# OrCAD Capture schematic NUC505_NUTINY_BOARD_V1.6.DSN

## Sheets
1 Block Diagram: size A; rev: 1.6; note: Block Diagram; note: NUC505 Tiny Board
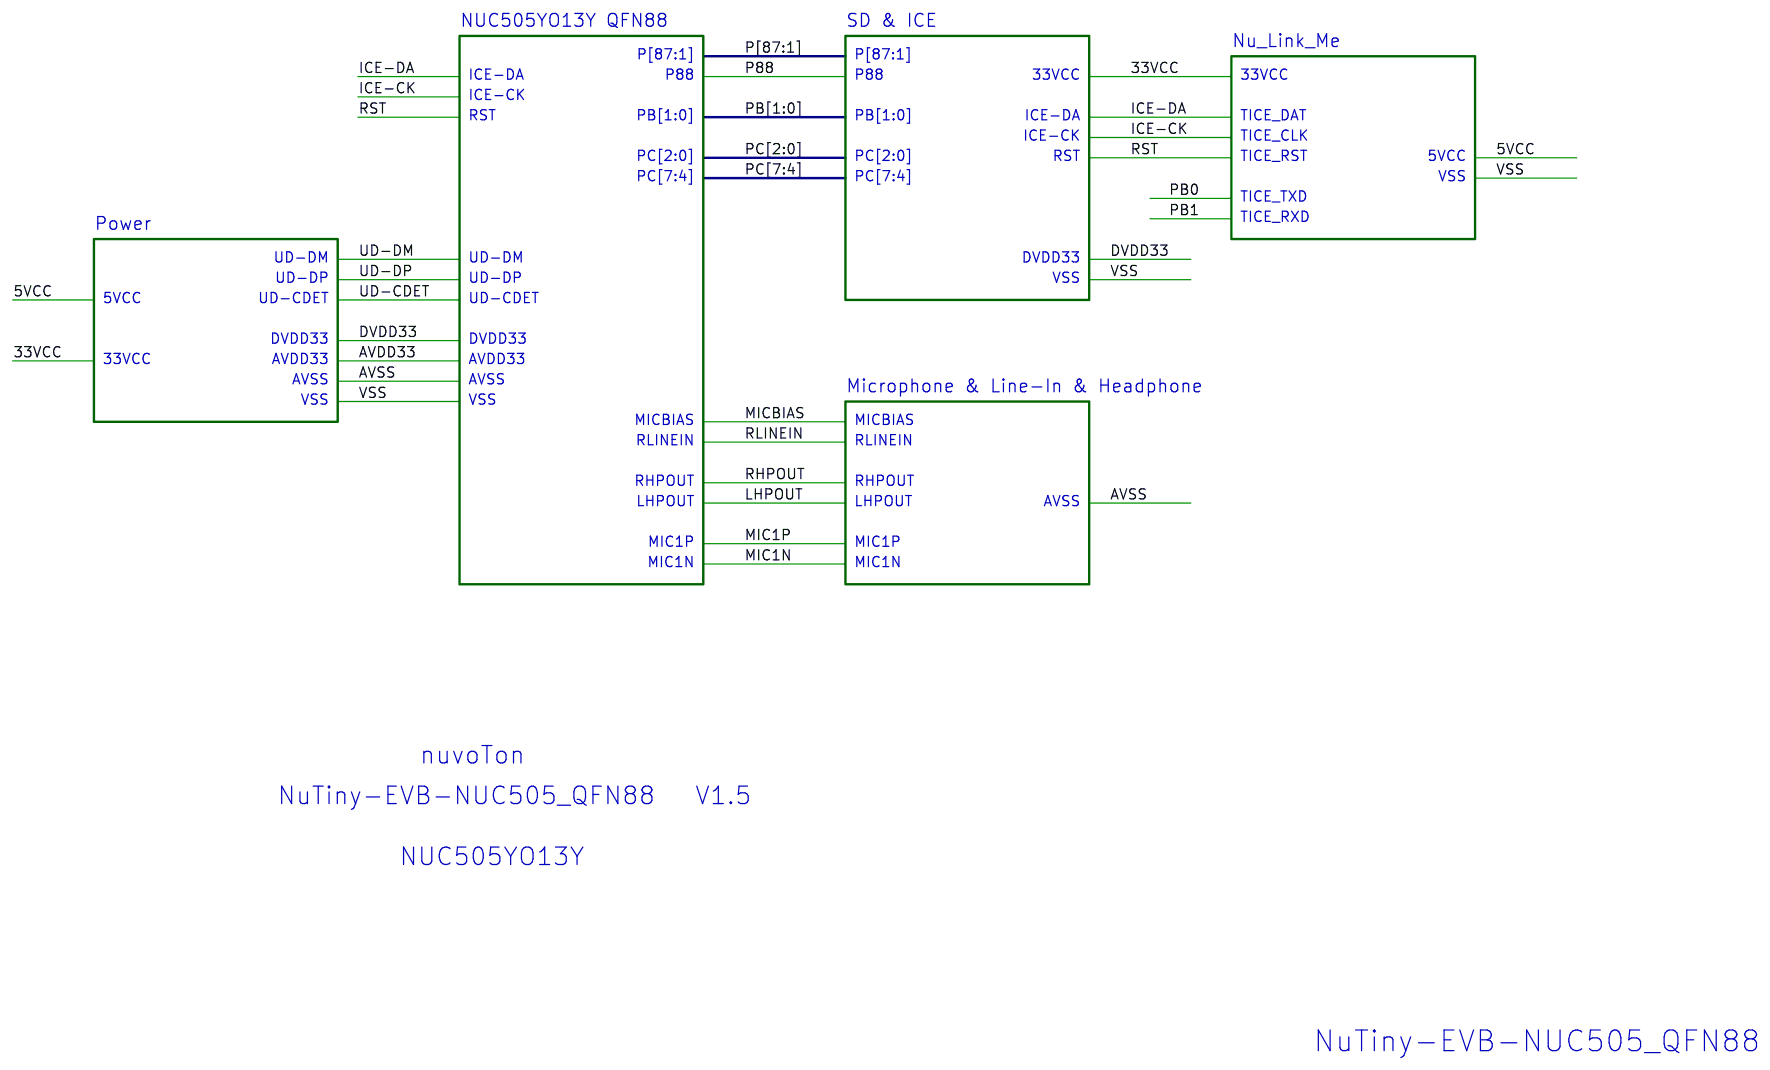
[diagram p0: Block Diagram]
2 Microphone&Line-In&Headphone: size A; note: Microphone&Line In&Headphone; block Microphone & Line-In & Headphone
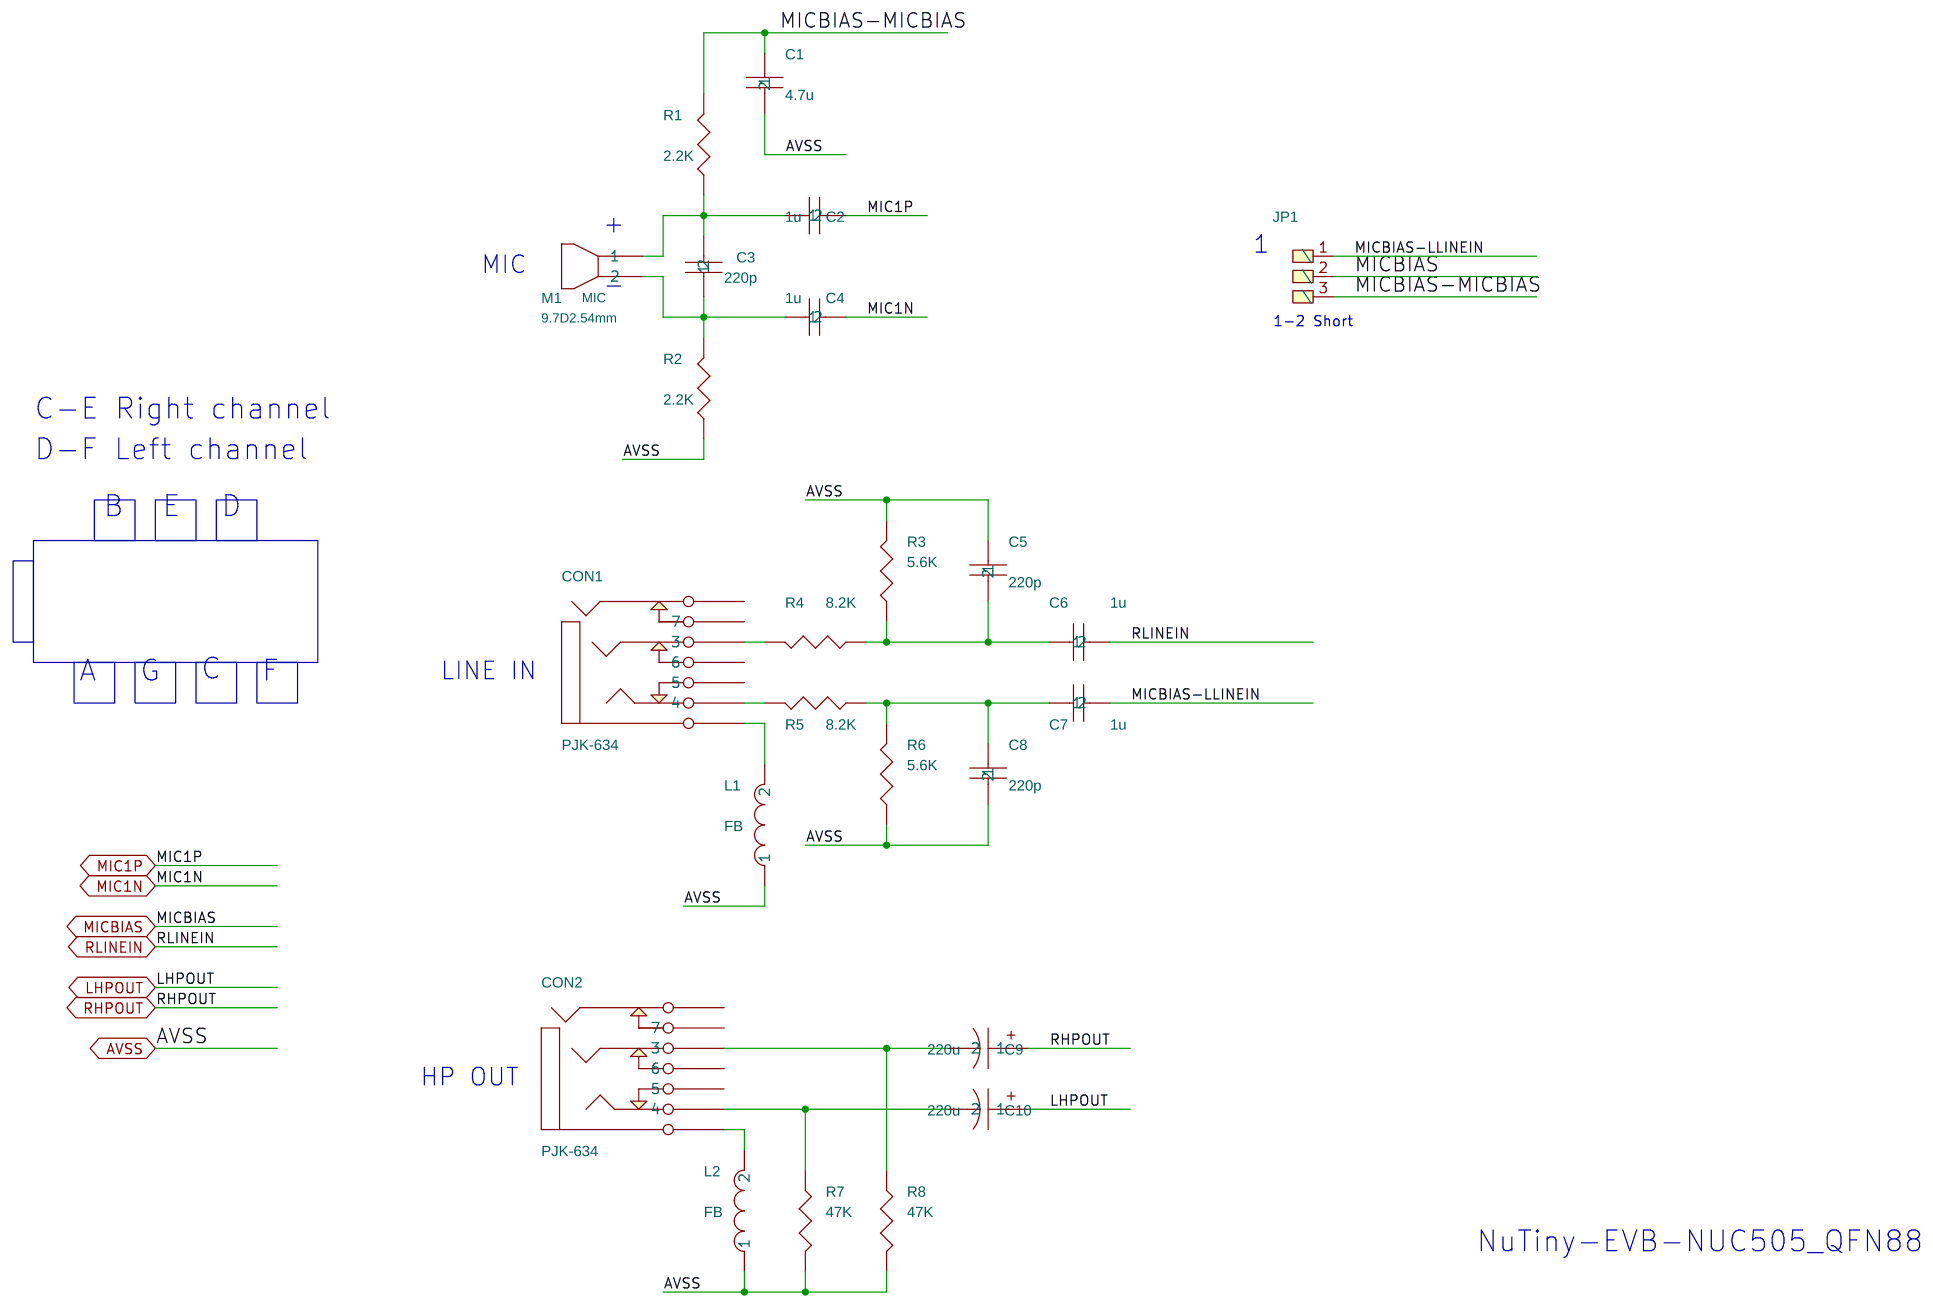
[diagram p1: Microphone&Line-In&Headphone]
3 Nu_Link_Me: size A4; note: Nu_Link_Me; block Nu_Link_Me
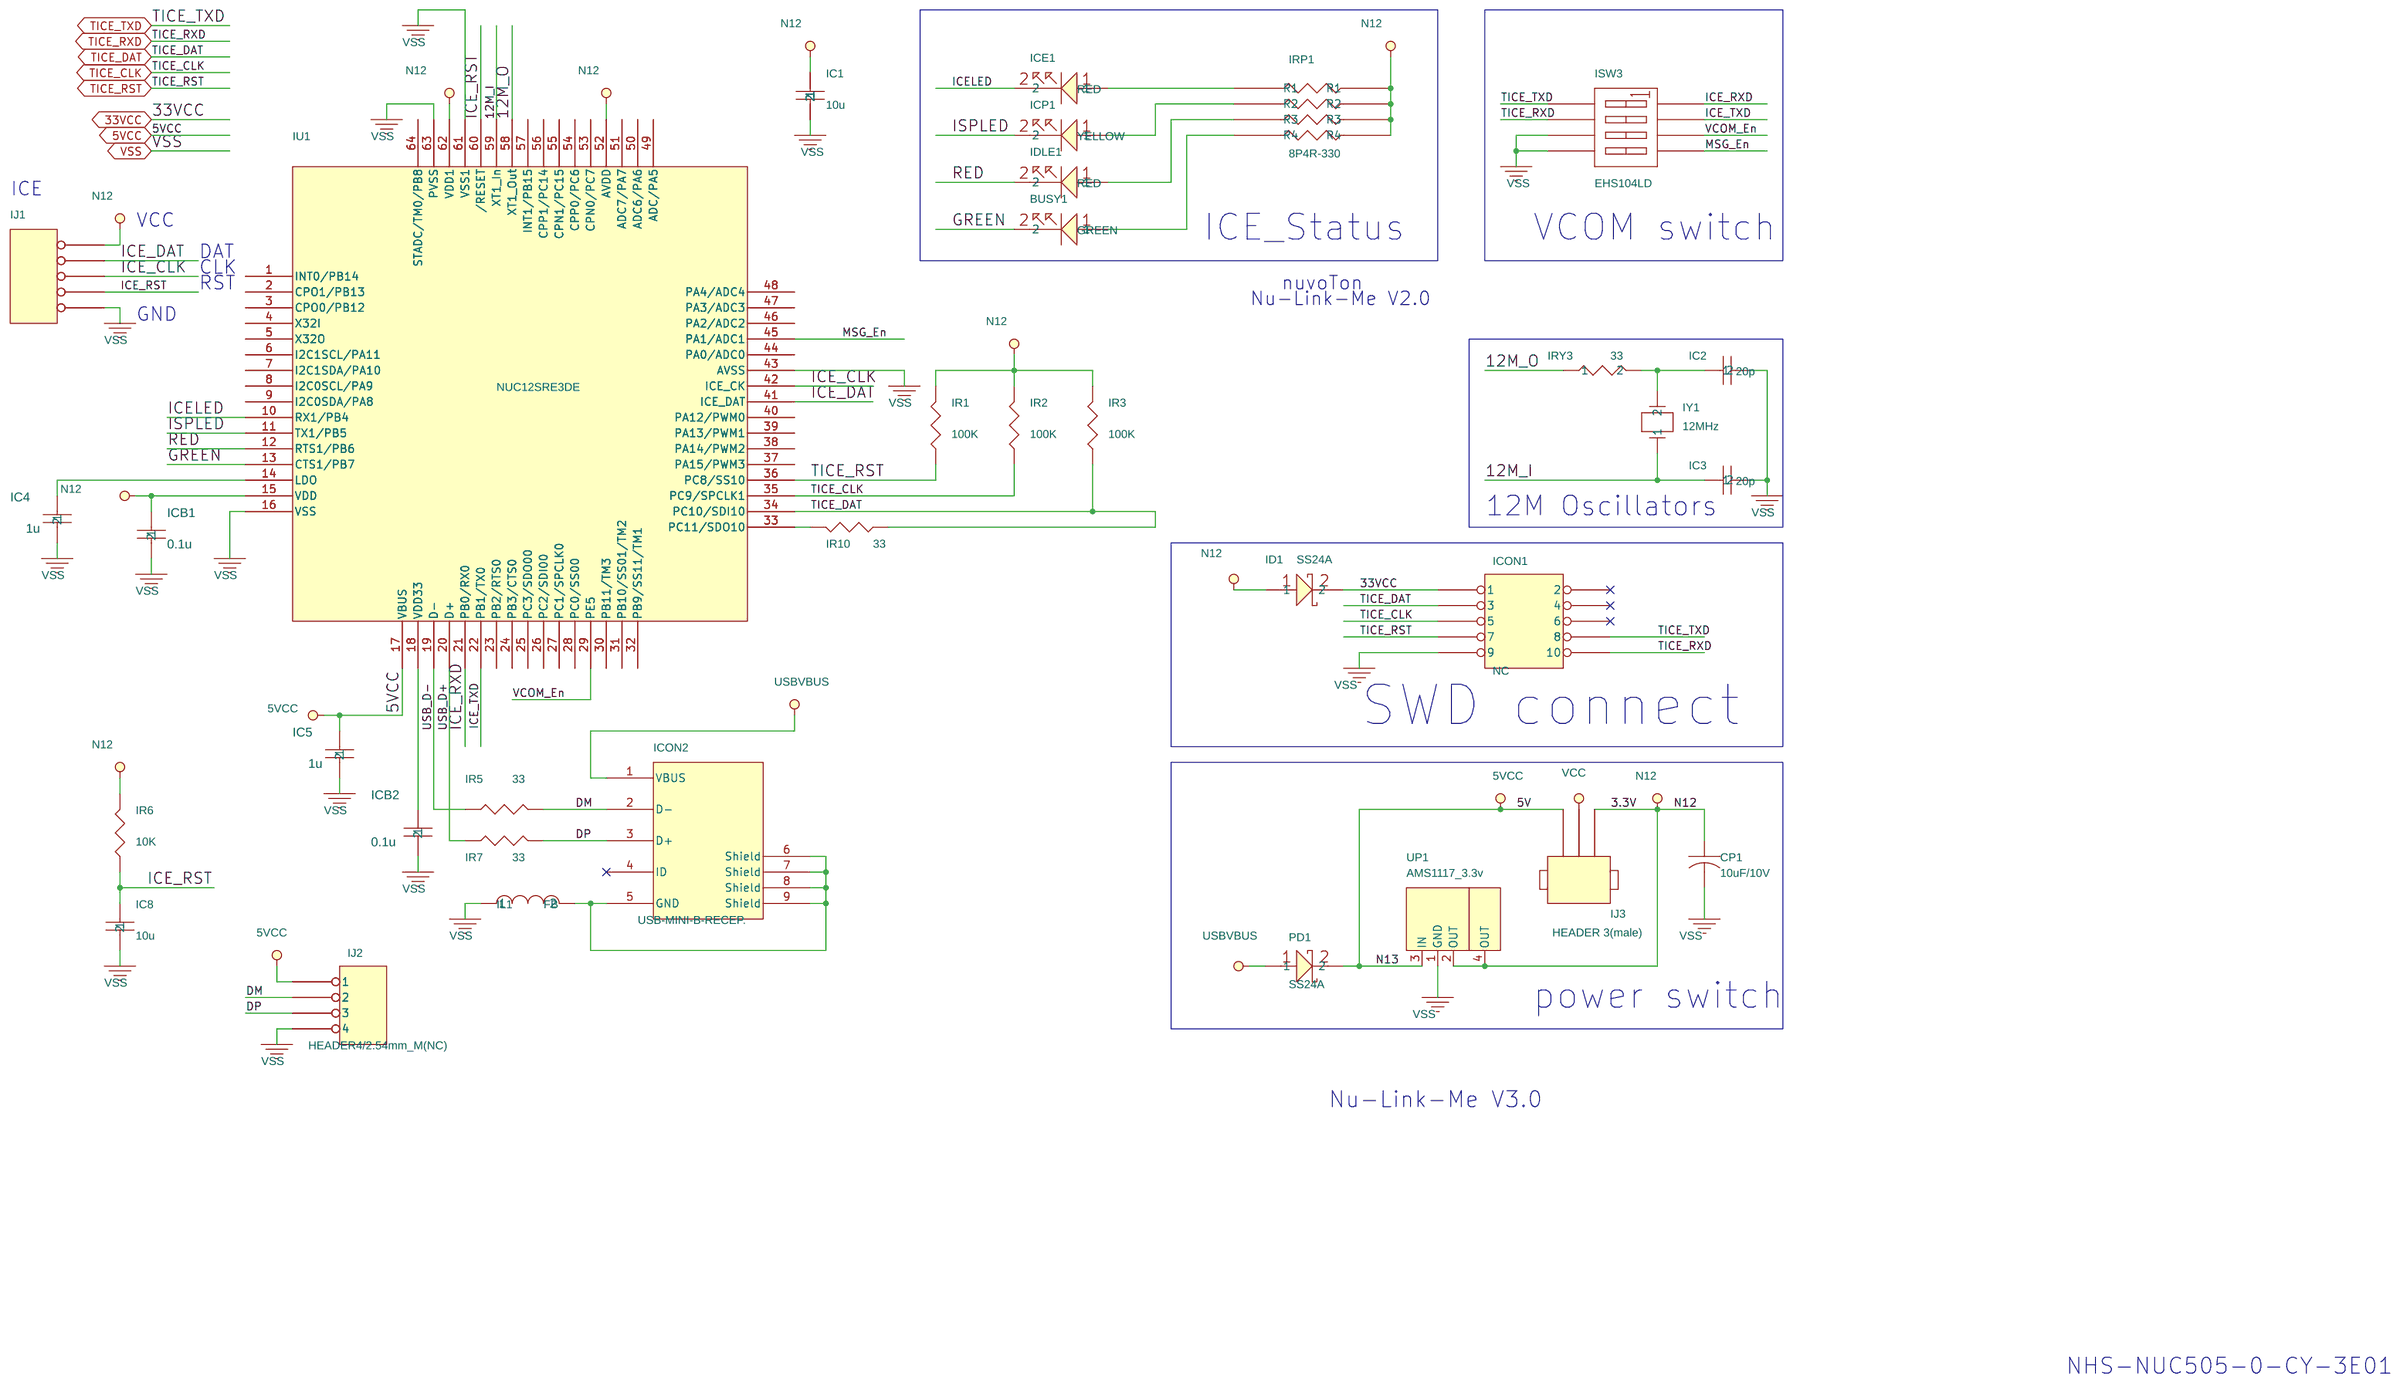
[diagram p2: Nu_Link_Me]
4 NUC505YO13Y QFN88: size A; note: NUC505YO13Y; block NUC505YO13Y QFN88
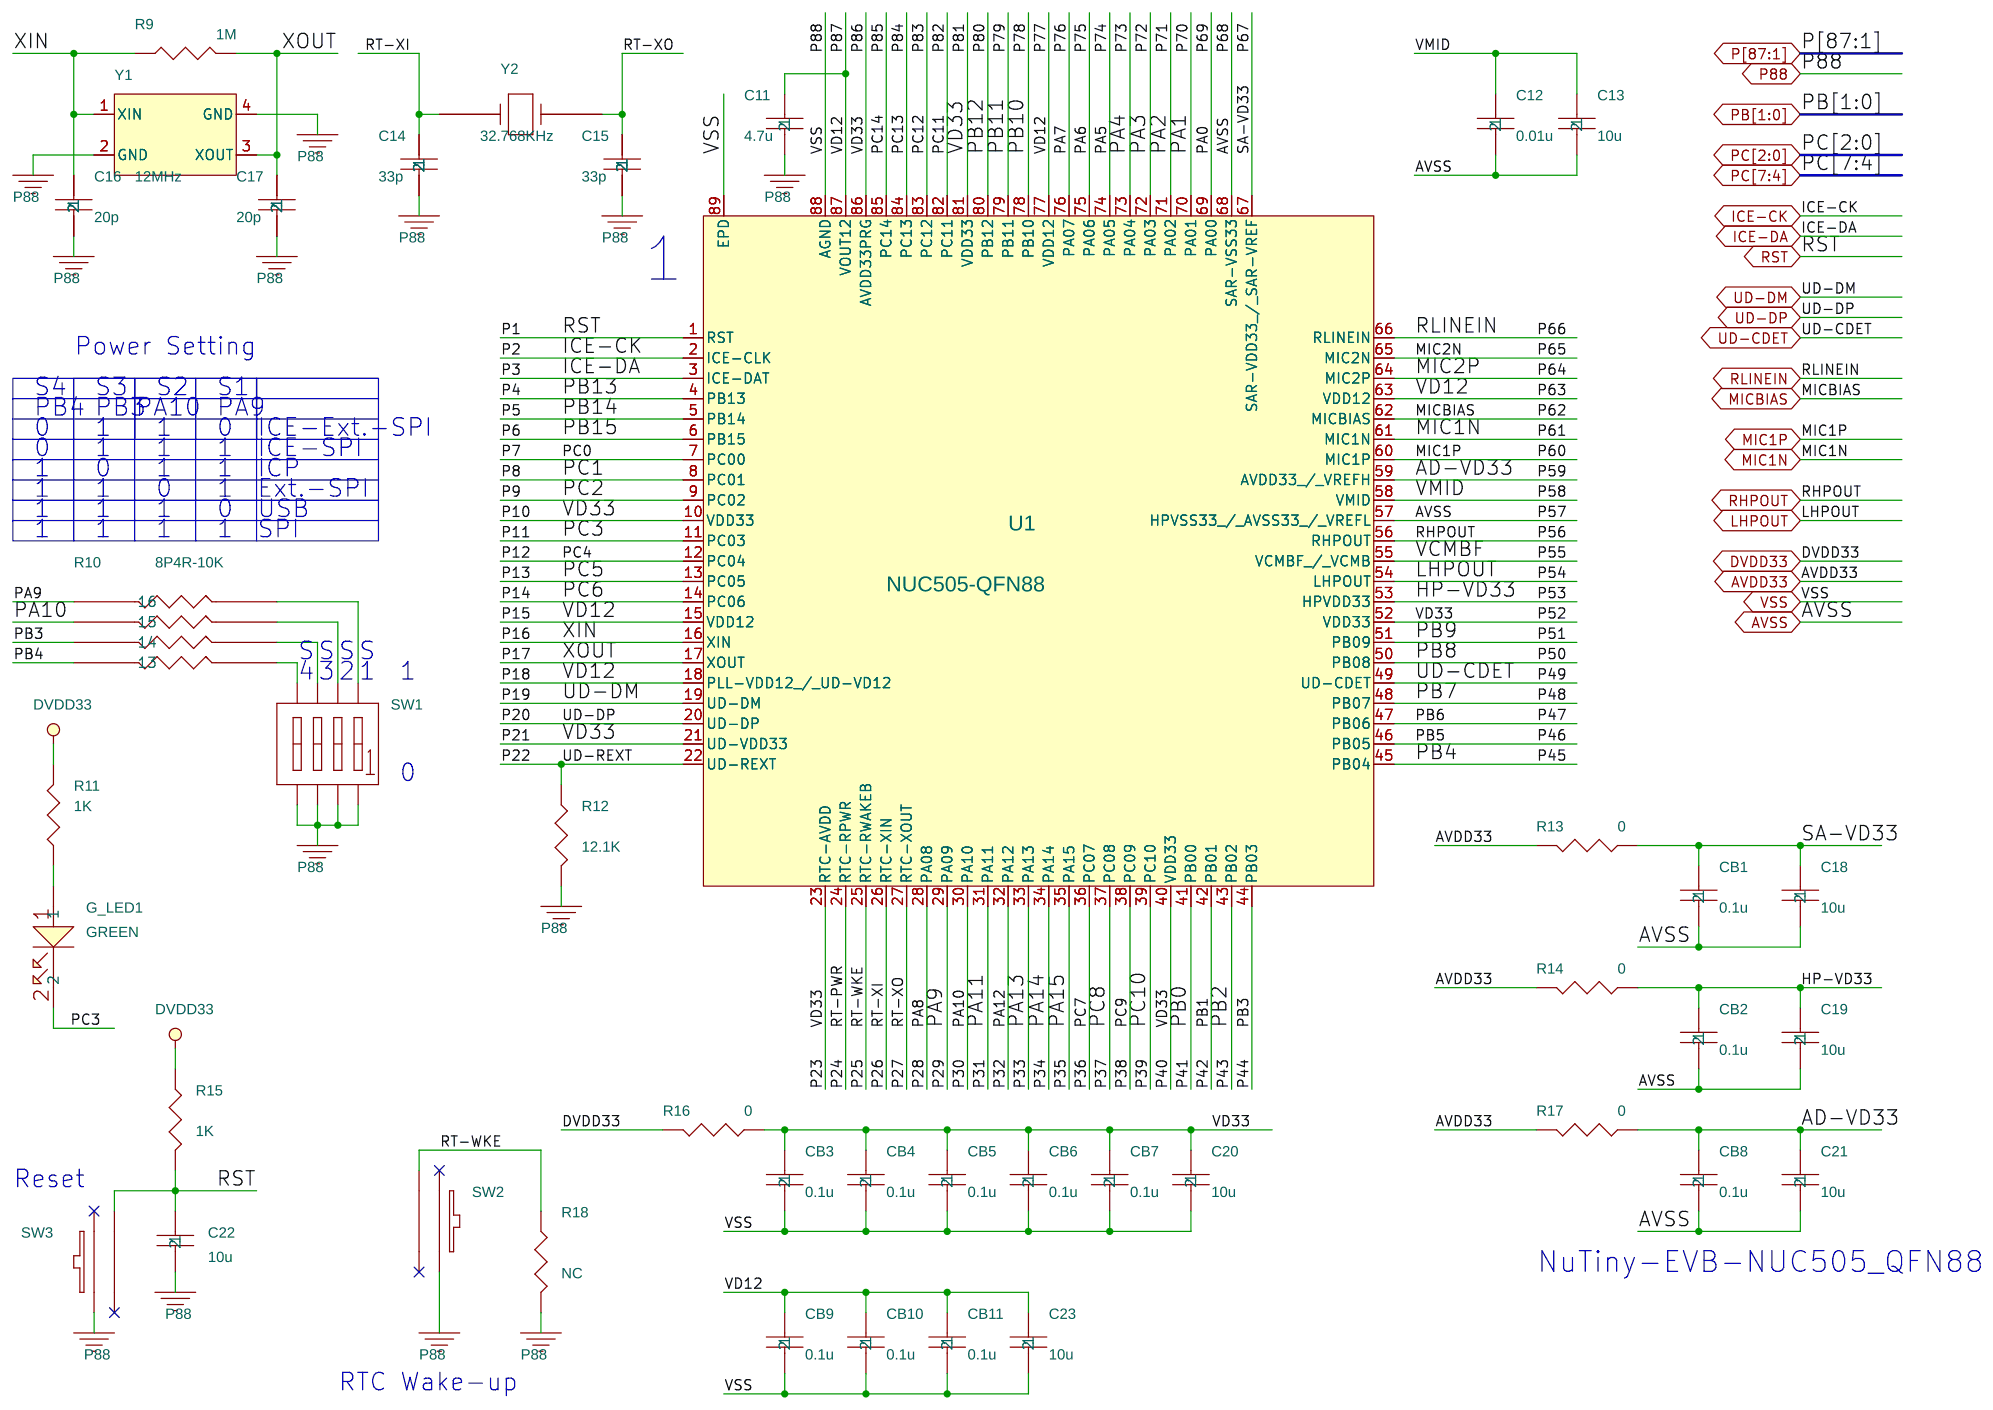
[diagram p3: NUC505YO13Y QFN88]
5 Power: size A; note: Power; block Power
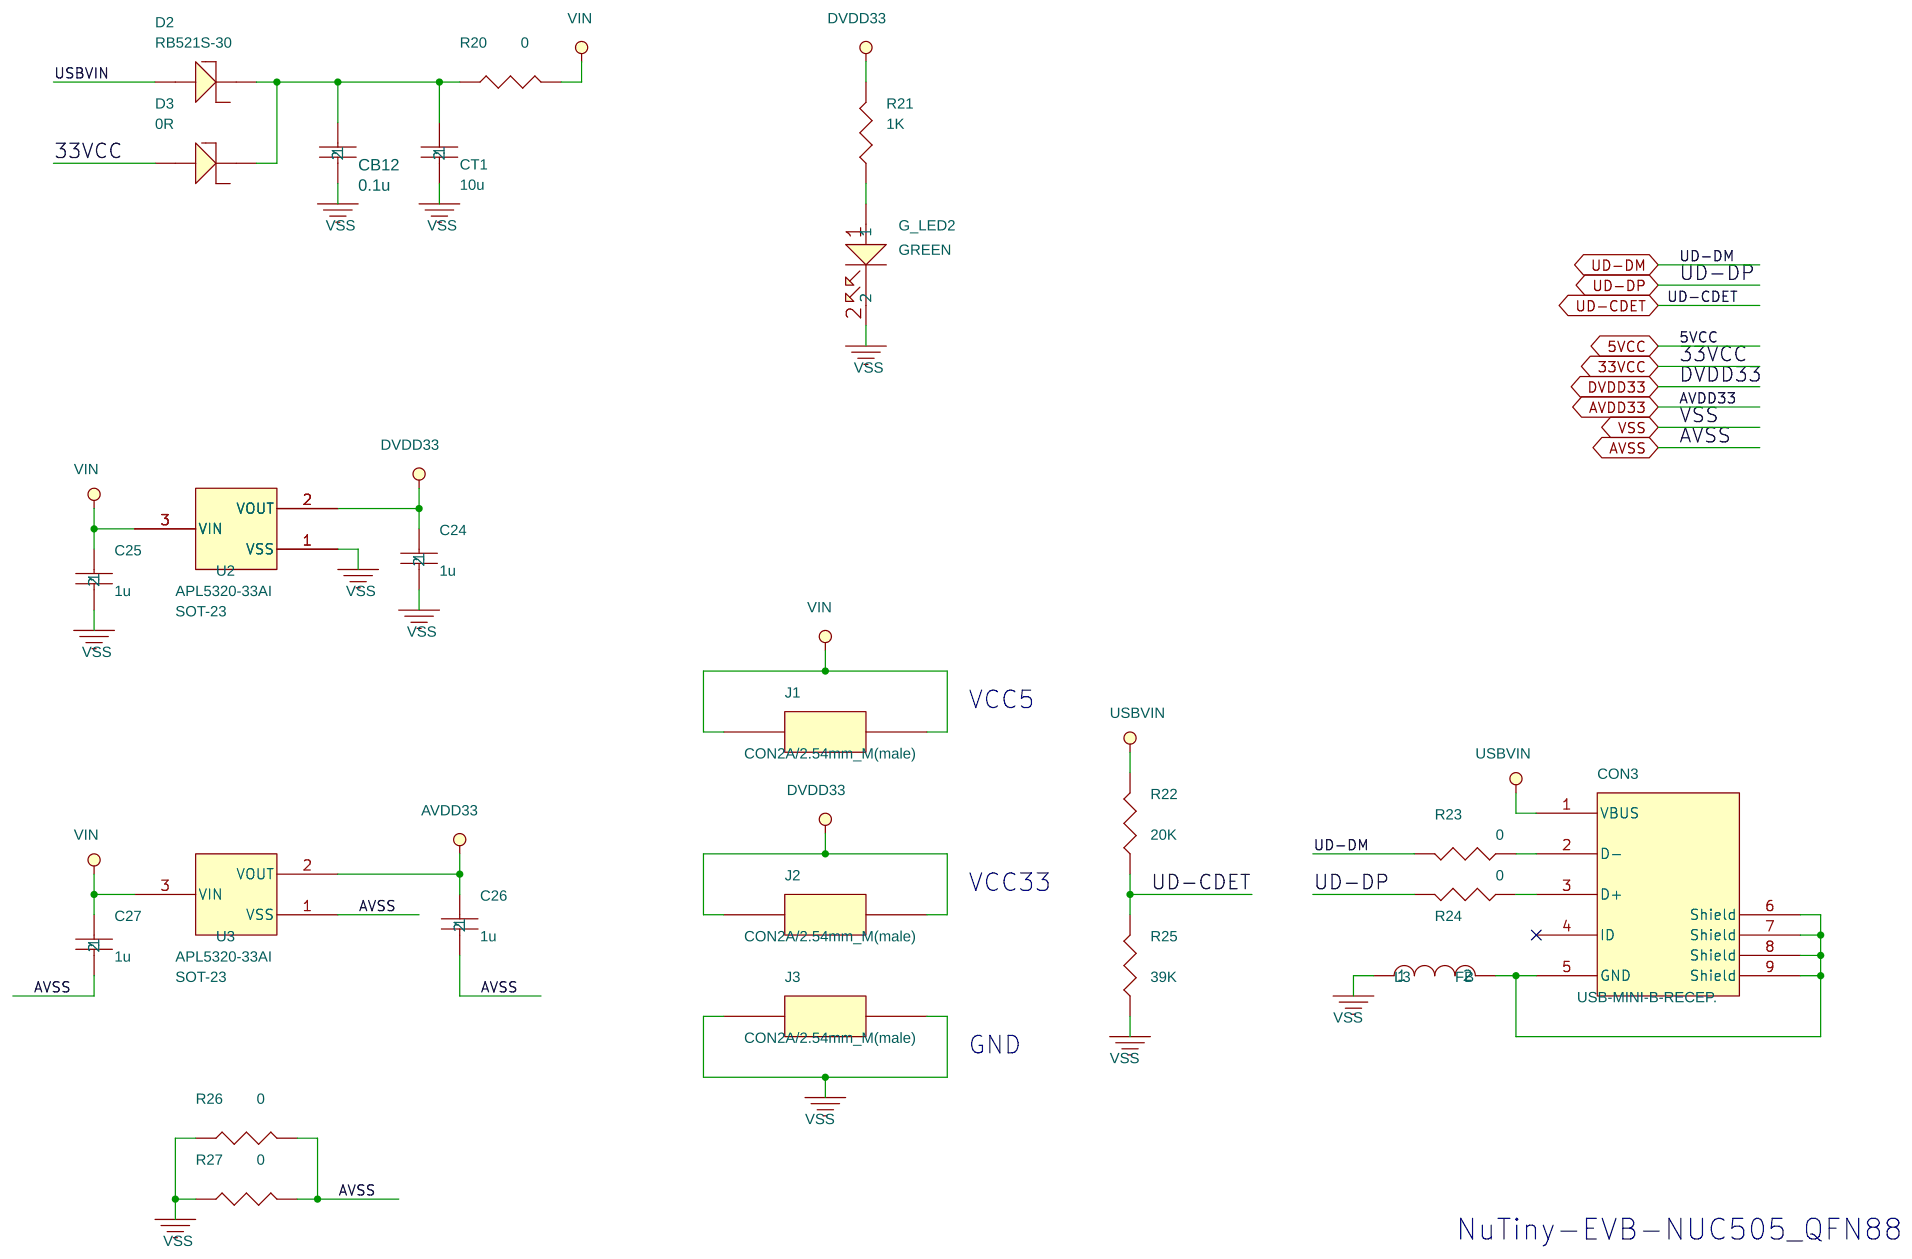
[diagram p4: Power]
6 SD & ICE: size A; note: SD & ICE; block SD & ICE
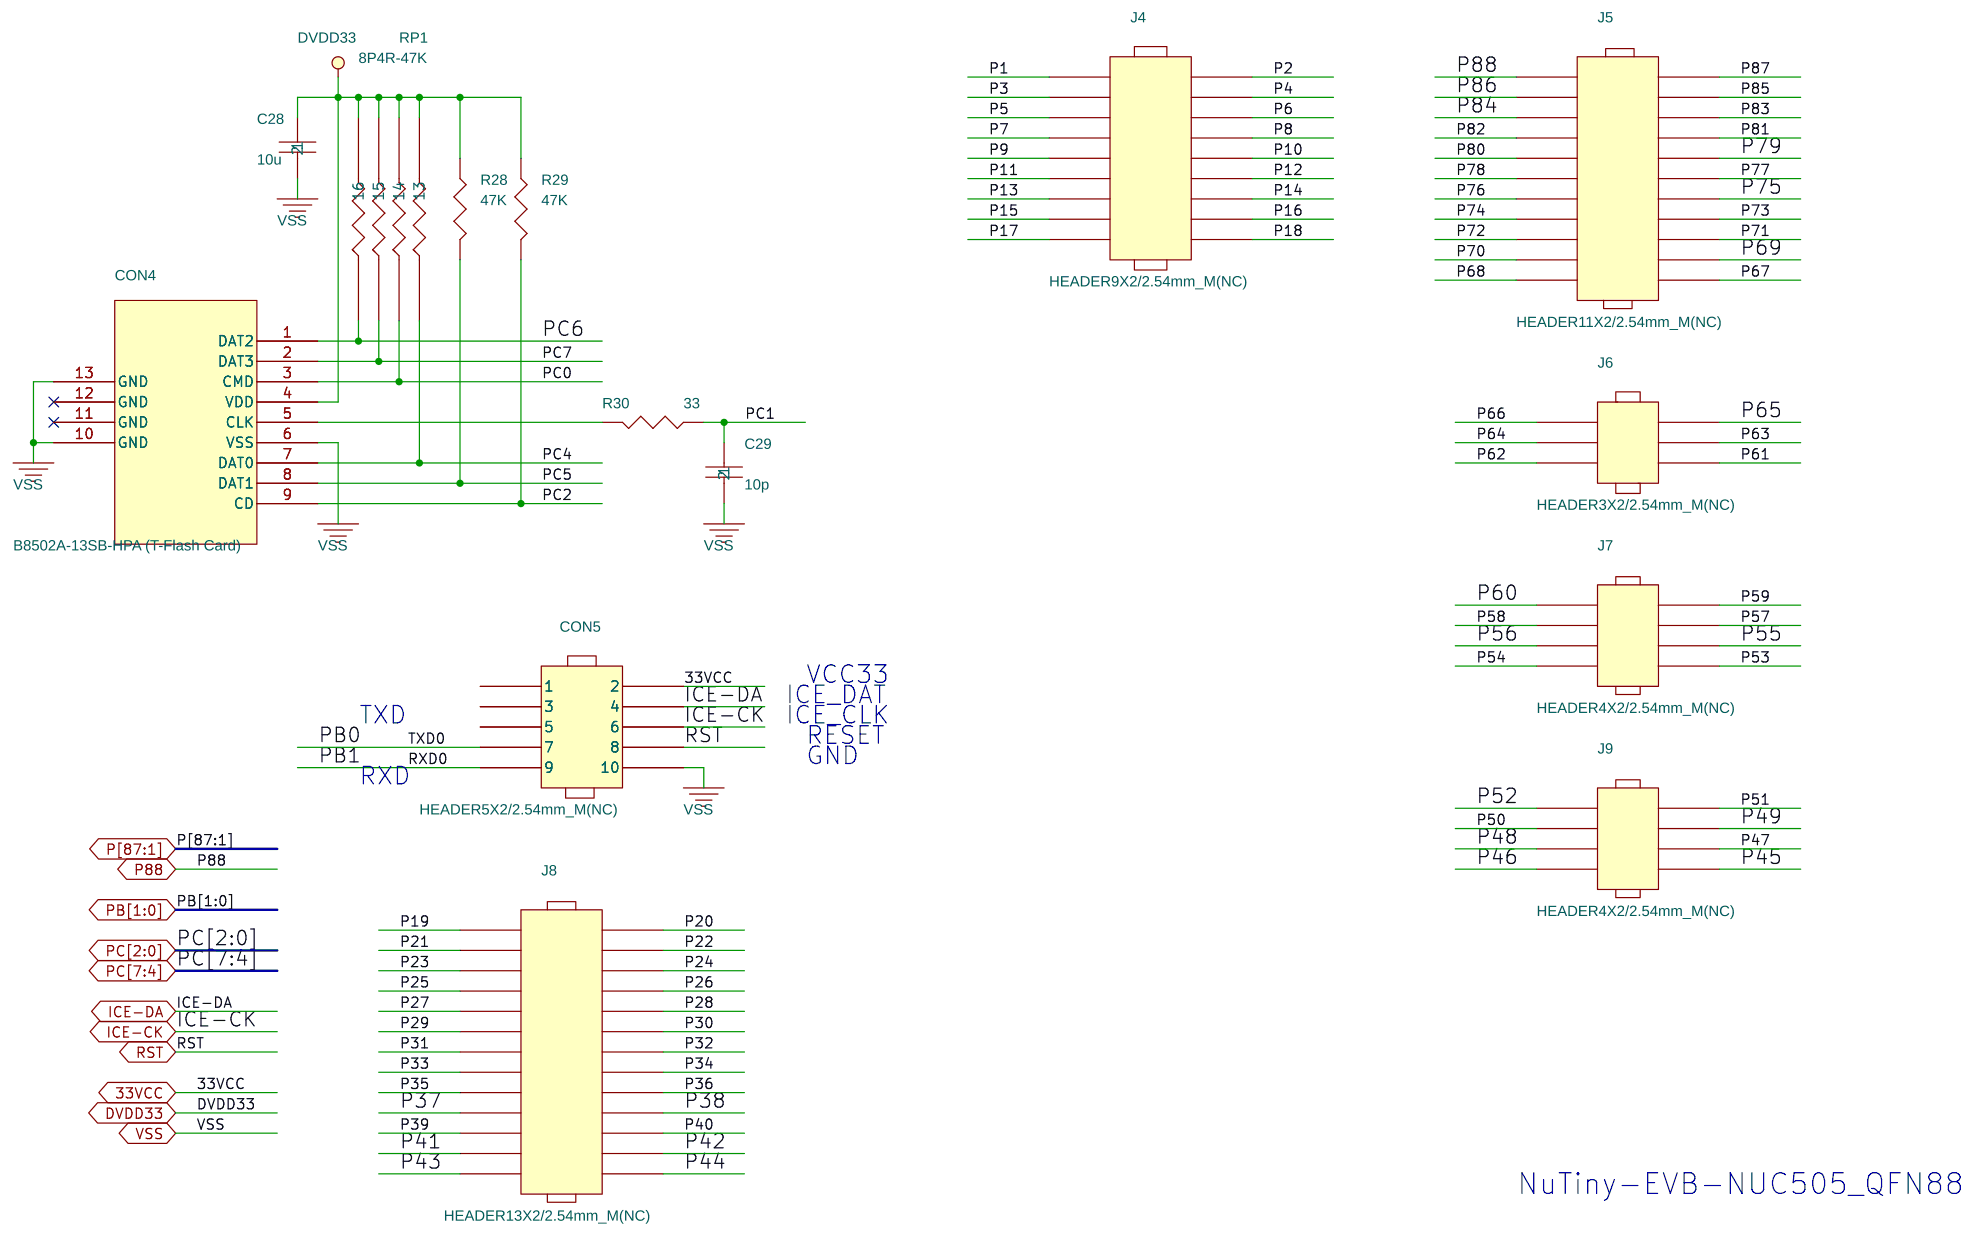
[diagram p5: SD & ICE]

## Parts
sheet Microphone&Line-In&Headphone
C1  4.7u  [C0603]
C2  1u  [C0603]
C3  220p  [C0603]
C4  1u  [C0603]
C5  220p  [C0603]
C6  1u  [C0603]
C7  1u  [C0603]
C8  220p  [C0603]
C9  220u  [CAP_B]
C10  220u  [CAP_B]
CON1  PJK-634  [PHONE-PJK-631]
CON2  PJK-634  [PHONE-PJK-631]
JP1  SW3PAD-S (1, 2 pin 0R)  [3P-1.2mm]
L1  FB  [L0603]
L2  FB  [L0603]
M1  MIC  [9.7D2.54mm]
R1  2.2K  [R0603]
R2  2.2K  [R0603]
R3  5.6K  [R0603]
R4  8.2K  [R0603]
R5  8.2K  [R0603]
R6  5.6K  [R0603]
R7  47K  [R0603]
R8  47K  [R0603]
sheet Nu_Link_Me
BUSY1  GREEN  [LED0805]
CP1  10uF/10V  [TANT-A]
IC1  10u  [C0603]
IC2  20p  [C0603]
IC3  20p  [C0603]
IC4  1u  [C0603]
IC5  1u  [C0603]
IC8  10u  [C0603]
ICB1  0.1u  [C0603]
ICB2  0.1u  [C0603]
ICE1  RED  [LED0805]
ICON1  NC  [HEADER5X2]
ICON2  USB-MINI-B-RECEP.  [USB_MINI_B]
ICP1  YELLOW  [LED0805]
ID1  SS24A  [RB060L]
IDLE1  RED  [LED0805]
IJ1  NC  [HEADER05]
IJ2  HEADER4/2.54mm_M(NC)
IJ3  HEADER 3(male)  [HEADER3]
IL1  FB  [L0603]
IR1  100K  [R0603]
IR2  100K  [R0603]
IR3  100K  [R0603]
IR5  33  [R0603]
IR6  10K  [R0603]
IR7  33  [R0603]
IR10  33  [R0603]
IRP1  8P4R-330  [8P4RA]
IRY3  33  [R0603]
ISW3  EHS104LD  [SW1X4]
IU1  NUC12SRE3DE  [NCU120_LQFP_64]
IY1  12MHz  [XTAL\LP\SMD]
PD1  SS24A  [RB060L]
UP1  AMS1117_3.3v  [SOT-223-1]
sheet NUC505YO13Y QFN88
C11  4.7u  [C0603]
C12  0.01u  [C0603]
C13  10u  [C0603]
C14  33p  [C0603]
C15  33p  [C0603]
C16  20p  [C0603]
C17  20p  [C0603]
C18  10u  [C0603]
C19  10u  [C0603]
C20  10u  [C0603]
C21  10u  [C0603]
C22  10u  [C0603]
C23  10u  [C0603]
CB1  0.1u  [C0603]
CB2  0.1u  [C0603]
CB3  0.1u  [C0603]
CB4  0.1u  [C0603]
CB5  0.1u  [C0603]
CB6  0.1u  [C0603]
CB7  0.1u  [C0603]
CB8  0.1u  [C0603]
CB9  0.1u  [C0603]
CB10  0.1u  [C0603]
CB11  0.1u  [C0603]
G_LED1  GREEN  [LED0805]
R9  1M  [R0603]
R10  8P4R-10K  [R8P4R\A]
R11  1K  [R0603]
R12  12.1K  [R0603]
R13  0  [R0603]
R14  0  [R0603]
R15  1K  [R0603]
R16  0  [R0603]
R17  0  [R0603]
R18  NC  [R0603]
SW1  SW SMD-4  [HPS604-E]
SW2  DSP  [STS-B5]
SW3  Up  [STS-B5]
U1  NUC505-QFN88  [QFN-88]
Y1  12MHz  [XRGBBCNANF-27M]
Y2  32.768KHz  [9HT9]
sheet Power
C24  1u  [C0603]
C25  1u  [C0603]
C26  1u  [C0603]
C27  1u  [C0603]
CB12  0.1u  [C0603]
CON3  USB-MINI-B-RECEP.  [USB_MINI_B]
CT1  10u  [C0603]
D2  RB521S-30  [SOD-523]
D3  0R  [SOD-523]
G_LED2  GREEN  [LED0805]
J1  CON2A/2.54mm_M(male)  [SIP/2P]
J2  CON2A/2.54mm_M(male)  [SIP/2P]
J3  CON2A/2.54mm_M(male)  [SIP/2P]
L3  FB  [L0603]
R20  0  [R0603]
R21  1K  [R0603]
R22  20K  [R0603]
R23  0  [R0603]
R24  0  [R0603]
R25  39K  [R0603]
R26  0  [R0603]
R27  0  [R0603]
U2  APL5320-33AI  [SOT-23]
U3  APL5320-33AI  [SOT-23]
sheet SD & ICE
C28  10u  [C0603]
C29  10p  [C0603]
CON4  B8502A-13SB-HPA (T-Flash Card)  [B8502A-13SB-HPA]
CON5  HEADER5X2/2.54mm_M(NC)  [HEADER5X2]
J4  HEADER9X2/2.54mm_M(NC)
J5  HEADER11X2/2.54mm_M(NC)
J6  HEADER3X2/2.54mm_M(NC)
J7  HEADER4X2/2.54mm_M(NC)
J8  HEADER13X2/2.54mm_M(NC)
J9  HEADER4X2/2.54mm_M(NC)
R28  47K  [R0603]
R29  47K  [R0603]
R30  33  [R0603]
RP1  8P4R-47K  [R8P4R\A]

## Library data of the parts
C1 = CAPACITOR_NON-POL_5
C2 = CAPACITOR_NON-POL_1
C3 = CAPACITOR_NON-POL
C4 = CAPACITOR_NON-POL_6
C5 = CAPACITOR_NON-POL_7
C6 = CAPACITOR_NON-POL_4
C7 = CAPACITOR_NON-POL_3
C8 = CAPACITOR_NON-POL_2
C9 = CAP-T_1
C10 = CAP-T
CON1 CON2 = PHONEJACK_STEREO_SW_PJK-634_1: Vendor: ÂEµX
JP1 = SW3PAD-S
L1 = INDUCTOR_1
IL1 L2 L3 = INDUCTOR
M1 = MICROPHONE_0
R1-R6 = RESISTOR
IR10 R7 R11 R25 R28 = R_1
IR1 R8 R18 R20 R30 = R
BUSY1 = LED_GREEN
CP1 = C_10uF_10V
C11 C26 IC1 = CAP_NP_3
IC2 = C_20p_1
IC3 = C_20p
C14 C25 IC4 = CAP_NP_2
C16 C27 IC5 = CAP_NP_1
C12 C28 IC8 = CAP-B
C17 C24 C29 ICB1 = CAP_NP
C15 CT1 ICB2 = CAP_NP_4
ICE1 = LED_RED_1
ICON1 = HEADER_5X2
CON3 ICON2 = USB_type_B_mini_connector
ICP1 = LED_YELLOW
ID1 = D_SS24A
G_LED1 G_LED2 IDLE1 = LED_RED
IJ1 = HEADER_5
IJ2 = HEADER_4
IJ3 = HEADER_3
IR2 R14 R21 = R_5
IR3 R13 R27 = R_4
IR5 R12 R24 = R_6
IR6 R16 R22 R29 = R_2
IR7 R17 R26 = R_3
IRP1 = 8P4R-330
IRY3 = R_33
ISW3 = SW_DIP-4_SM
IU1 = NCU120_LQFP_0
IY1 = Xtal_12MHz
PD1 = D_SS24A_1
UP1 = TO-247_Regulator_10
C13 = CAP-B_14
C18 = CAP-B_4
C19 = CAP-B_11
C20 = CAP-B_9
C21 = CAP-B_16
C22 CB12 = CAP_NP_5
C23 = CAP-B_1
CB1 = CAP-B_2
CB2 = CAP-B_8
CB3 = CAP-B_13
CB4 = CAP-B_3
CB5 = CAP-B_5
CB6 = CAP-B_6
CB7 = CAP-B_7
CB8 = CAP-B_15
CB9 = CAP-B_10
CB10 = CAP-B_12
CB11 = CAP-B_17
R9 = R_8
R10 RP1 = 4R_0
R15 R23 = R_7
SW1 = SW_DIP-4_0
SW2 = SW-S_1
SW3 = SW-S
U1 = W55FA93_COB218_83
Y1 = Crystal_SMD_2
Y2 = MA306_SM_1
D2 D3 = ZENAR_0: Package: D
J1-J3 = CON2A
U2 U3 = XC6206P182MR
CON4 = B8502A-13SB-HPA_(T-Flash_Card)
CON5 = HEADER_5X2_v2
J4 = HEADER_9X2
J5 = HEADER_11X2
J6 = HEADER_3X2
J7 J9 = HEADER_4X2
J8 = HEADER_13X2

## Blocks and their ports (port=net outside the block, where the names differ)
NUC505YO13Y QFN88 = schematic NUC505YO13Y QFN88, on sheet Block Diagram: RST, VSS, AVDD33, ICE-CK, ICE-DA, MICBIAS, RLINEIN, RHPOUT, LHPOUT, UD-DM, UD-DP, UD-CDET, P[87:1], PC[7:4], PC[2:0], PB[1:0], MIC1P, MIC1N, DVDD33, P88=VSS, AVSS
Power = schematic Power, on sheet Block Diagram: VSS, AVDD33, DVDD33, UD-DM, UD-DP, UD-CDET, 5VCC, 33VCC, AVSS
SD & ICE = schematic SD & ICE, on sheet Block Diagram: PC[2:0], PB[1:0], PC[7:4], ICE-DA, VSS, DVDD33, P[87:1], ICE-CK, RST, 33VCC, P88=VSS
Nu_Link_Me = schematic Nu_Link_Me, on sheet Block Diagram: TICE_DAT=ICE-DA, TICE_CLK=ICE-CK, TICE_RST=RST, 5VCC, TICE_RXD=PB1, TICE_TXD=PB0, VSS, 33VCC
Microphone & Line-In & Headphone = schematic Microphone&Line-In&Headphone, on sheet Block Diagram: MICBIAS, RLINEIN, RHPOUT, LHPOUT, MIC1P, MIC1N, AVSS

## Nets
5VCC: IC5.1 IJ2.1 IJ3.3 IU1.17(VBUS) PD1.2 UP1.3(IN)
33VCC: CON5.2 D3.1 ICON1.1 ID1.2 IJ3.2
AVDD33: C26.1 R13.2 R14.2 R17.2 U3.2(VOUT)
AVSS: C1.2 C5.1 C8.2 C12.2 C13.2 C18.2 C19.2 C21.2 C26.2 C27.2 CB1.2 CB2.2 CB8.2 J5.2 J7.5 L1.1 L2.1 R2.1 R3.2 R6.1 R7.2 R8.2 R26.2 R27.2 U1.57(HPVSS33_/_AVSS33_/_VREFL) U1.68(SAR-VSS33) U3.1(VSS)
DVDD33: C24.1 C28.1 CON4.4(VDD) J2.1 J2.2 R11.2 R15.1 R16.2 R21.2 R28.1 R29.1 RP1.5(13) RP1.6(14) RP1.7(15) RP1.8(16) U2.2(VOUT)
VIN: C25.1 C27.1 J1.1 J1.2 R20.2 U2.3(VIN) U3.3(VIN)
VSS: C11.2 C14.2 C15.2 C16.2 C17.2 C20.2 C22.2 C23.2 C24.2 C25.2 C28.2 C29.2 CB3.2 CB4.2 CB5.2 CB6.2 CB7.2 CB9.2 CB10.2 CB11.2 CB12.2 CON4.6(VSS) CON4.10(GND) CON4.13(GND) CON5.10 CP1.2 CT1.2 G_LED2.2 IC1.2 IC2.2 IC3.2 IC4.2 IC5.2 IC8.2 ICB1.2 ICB2.2 ICON1.9 IJ1.5 IJ2.4 IL1.1 ISW3.3(A3) ISW3.4(A4) IU1.16(VSS) IU1.43(AVSS) IU1.61(VSS1) IU1.63(PVSS) J3.1 J3.2 J5.22 L3.1 R12.2 R18.2 R25.1 R26.1 R27.1 SW1.5(B4) SW1.6(B3) SW1.7(B2) SW1.8(B1) SW2.4 SW3.4 U1.88(AGND) U1.89(EPD) U2.1(VSS) UP1.1(GND) Y1.2(GND) Y1.4(GND)
ICE-CK: CON5.6 ICON1.5 IR2.1 IU1.35(PC9/SPCLK1) J4.2 U1.2(ICE-CLK)
ICE-DA: CON5.4 ICON1.3 IR3.1 IR10.1 IU1.34(PC10/SDI10) J4.3 U1.3(ICE-DAT)
ICEVCC: CP1.1 IC1.1 ICB1.1 ID1.1 IJ1.1 IJ3.1 IR1.2 IR2.2 IR3.2 IR6.2 IRP1.2(R1) IRP1.4(R2) IRP1.6(R3) IRP1.8(R4) IU1.15(VDD) IU1.52(AVDD) IU1.62(VDD1) UP1.2(OUT) UP1.4(OUT)
LHPOUT: C10.1 J7.2 U1.54(LHPOUT)
MIC1N: C4.2 J6.1 U1.61(MIC1N)
MIC1P: C2.2 J7.8 U1.60(MIC1P)
MICBIAS: J6.2 JP1.2(\) U1.62(MICBIAS)
Microphone & Line-In & Headphone/MICBIAS-LLINEIN: C7.2 JP1.1(\)
Microphone & Line-In & Headphone/MICBIAS-MICBIAS: C1.1 JP1.3(\) R1.2
Nu_Link_Me/12M_I: IC3.1 IU1.59(XT1_In) IY1.1
Nu_Link_Me/12M_O: IRY3.1 IU1.58(XT1_Out)
Nu_Link_Me/DM: ICON2.2(D-) IJ2.2 IR5.2
Nu_Link_Me/DP: ICON2.3(D+) IJ2.3 IR7.2
Nu_Link_Me/GREEN: BUSY1.2 IU1.13(CTS1/PB7)
Nu_Link_Me/ICE_CLK: IJ1.3 IU1.42(ICE_CK)
Nu_Link_Me/ICE_DAT: IJ1.2 IU1.41(ICE_DAT)
Nu_Link_Me/ICE_RST: IC8.1 IJ1.4 IR6.1 IU1.60(/RESET)
Nu_Link_Me/ICE_RXD: ISW3.8(B1) IU1.21(PB0/RX0)
Nu_Link_Me/ICE_TXD: ISW3.7(B2) IU1.22(PB1/TX0)
Nu_Link_Me/ICELED: ICE1.2 IU1.10(RX1/PB4)
Nu_Link_Me/ISPLED: ICP1.2 IU1.11(TX1/PB5)
Nu_Link_Me/MSG_En: ISW3.5(B4) IU1.45(PA1/ADC1)
Nu_Link_Me/RED: IDLE1.2 IU1.12(RTS1/PB6)
Nu_Link_Me/USB_D+: IR7.1 IU1.20(D+)
Nu_Link_Me/USB_D-: IR5.1 IU1.19(D-)
Nu_Link_Me/VCOM_En: ISW3.6(B3) IU1.29(PE5)
P4: J4.4 U1.4(PB13)
P5: J4.5 U1.5(PB14)
P6: J4.6 U1.6(PB15)
P7: CON4.3(CMD) J4.7 RP1.3 U1.7(PC00)
P8: C29.1 J4.8 R30.1 U1.8(PC01)
P9: CON4.9(CD) J4.9 R29.2 U1.9(PC02)
P10: C20.1 CB3.1 CB4.1 CB5.1 CB6.1 CB7.1 J4.10 J5.15 J5.20 J8.3 J8.5 J8.22 J9.8 R16.1 U1.10(VDD33) U1.21(UD-VDD33) U1.23(RTC-AVDD) U1.40(VDD33) U1.52(VDD33) U1.81(VDD33) U1.86(AVDD33PRG)
P11: G_LED1.2 J4.11 U1.11(PC03)
P12: CON4.7(DAT0) J4.12 RP1.4 U1.12(PC04)
P13: CON4.8(DAT1) J4.13 R28.2 U1.13(PC05)
P14: CON4.1(DAT2) J4.14 RP1.1 U1.14(PC06)
P15: C11.1 C23.1 CB9.1 CB10.1 CB11.1 J4.15 J4.18 J5.11 J5.21 J6.3 U1.15(VDD12) U1.18(PLL-VDD12_/_UD-VD12) U1.63(VDD12) U1.77(VDD12) U1.87(VOUT12)
P16: C16.1 J4.16 R9.1 U1.16(XIN) Y1.1(XIN)
P17: C17.1 J4.17 R9.2 U1.17(XOUT) Y1.3(XOUT)
P22: J8.4 R12.1 U1.22(UD-REXT)
P24: J8.6 U1.24(RTC-RPWR)
P25: J8.7 R18.1 SW2.1 U1.25(RTC-RWAKEB)
P26: C14.1 J8.8 U1.26(RTC-XIN) Y2.2
P27: C15.1 J8.9 U1.27(RTC-XOUT) Y2.1
P28: J8.10 U1.28(PA08)
P29: J8.11 R10.8(16) U1.29(PA09)
P30: J8.12 R10.7(15) U1.30(PA10)
P31: J8.13 U1.31(PA11)
P32: J8.14 U1.32(PA12)
P33: J8.15 U1.33(PA13)
P34: J8.16 U1.34(PA14)
P35: J8.17 U1.35(PA15)
P36: CON4.2(DAT3) J8.18 RP1.2 U1.36(PC07)
P37: J8.19 U1.37(PC08)
P38: J8.20 U1.38(PC09)
P39: J8.21 U1.39(PC10)
P43: J8.25 U1.43(PB02)
P44: J8.26 R10.6(14) U1.44(PB03)
P45: J9.1 R10.5(13) U1.45(PB04)
P46: J9.2 U1.46(PB05)
P47: J9.3 U1.47(PB06)
P48: J9.4 U1.48(PB07)
P50: J9.6 U1.50(PB08)
P51: J9.7 U1.51(PB09)
P53: C19.1 CB2.1 J7.1 R14.1 U1.53(HPVDD33)
P55: J7.3 U1.55(VCMBF_/_VCMB)
P58: C12.1 C13.1 J7.6 U1.58(VMID)
P59: C21.1 CB8.1 J7.7 R17.1 U1.59(AVDD33_/_VREFH)
P64: J6.4 U1.64(MIC2P)
P65: J6.5 U1.65(MIC2N)
P67: C18.1 CB1.1 J5.1 R13.1 U1.67(SAR-VDD33_/_SAR-VREF)
P69: J5.3 U1.69(PA00)
P70: J5.4 U1.70(PA01)
P71: J5.5 U1.71(PA02)
P72: J5.6 U1.72(PA03)
P73: J5.7 U1.73(PA04)
P74: J5.8 U1.74(PA05)
P75: J5.9 U1.75(PA06)
P76: J5.10 U1.76(PA07)
P78: J5.12 U1.78(PB10)
P79: J5.13 U1.79(PB11)
P80: J5.14 U1.80(PB12)
P82: J5.16 U1.82(PC11)
P83: J5.17 U1.83(PC12)
P84: J5.18 U1.84(PC13)
P85: J5.19 U1.85(PC14)
PB0: CON5.7 ICON1.8 ISW3.1(A1) J8.23 U1.41(PB00)
PB1: CON5.9 ICON1.10 ISW3.2(A2) J8.24 U1.42(PB01)
RHPOUT: C9.1 J7.4 U1.56(RHPOUT)
RLINEIN: C6.2 J6.6 U1.66(RLINEIN)
RST: C22.1 CON5.8 ICON1.7 IR1.1 IU1.36(PC8/SS10) J4.1 R15.2 SW3.1 U1.1(RST)
UD-CDET: J9.5 R22.1 R25.2 U1.49(UD-CDET)
UD-DM: J8.1 R23.2 U1.19(UD-DM)
UD-DP: J8.2 R24.2 U1.20(UD-DP)
USBVBUS: ICON2.1(VBUS) PD1.1
USBVIN: CON3.1(VBUS) D2.1 R22.2
Microphone & Line-In & Headphone/N16829119: CON1.D(4) R5.2
Microphone & Line-In & Headphone/N16829121: CON1.C(3) R4.2
Microphone & Line-In & Headphone/N16829123: CON1.A L1.2
Microphone & Line-In & Headphone/N16833437: C10.2 CON2.D(4) R7.1
Microphone & Line-In & Headphone/N16833439: C9.2 CON2.C(3) R8.1
Microphone & Line-In & Headphone/N16833491: CON2.A L2.2
Microphone & Line-In & Headphone/N16834962: C7.1 C8.1 R5.1 R6.2
Microphone & Line-In & Headphone/N16835076: C5.2 C6.1 R3.1 R4.1
Microphone & Line-In & Headphone/N16840633: C2.1 C3.2 M1.1 R1.1
Microphone & Line-In & Headphone/N16840719: C3.1 C4.1 M1.2 R2.2
Nu_Link_Me/N16779284: IC4.1 IU1.14(LDO)
Nu_Link_Me/N16779353: ICB2.1 IU1.18(VDD33)
Nu_Link_Me/N16791743: IR10.2 IU1.33(PC11/SDO10)
Nu_Link_Me/N16813302: ICON2.5(GND) ICON2.6(Shield) ICON2.7(Shield) ICON2.8(Shield) ICON2.9(Shield) IL1.2
Nu_Link_Me/N16833007: BUSY1.1 IRP1.7(R4)
Nu_Link_Me/N16833009: IDLE1.1 IRP1.5(R3)
Nu_Link_Me/N16833011: ICE1.1 IRP1.1(R1)
Nu_Link_Me/N16833020: ICP1.1 IRP1.3(R2)
Nu_Link_Me/N16833356: IC2.1 IRY3.2 IY1.2
NUC505YO13Y QFN88/N17810613: R10.4 SW1.4(A4)
NUC505YO13Y QFN88/N17810641: R10.3 SW1.3(A3)
NUC505YO13Y QFN88/N17810669: R10.2 SW1.2(A2)
NUC505YO13Y QFN88/N17810697: R10.1 SW1.1(A1)
NUC505YO13Y QFN88/N17818963: G_LED1.1 R11.1
Power/N16894920: CON3.5(GND) CON3.6(Shield) CON3.7(Shield) CON3.8(Shield) CON3.9(Shield) L3.2
Power/N16894960: CON3.2(D-) R23.1
Power/N16894962: CON3.3(D+) R24.1
Power/N16928379: CB12.1 CT1.1 D2.2 D3.2 R20.1
Power/N16930441: G_LED2.1 R21.1
SD & ICE/N16842765: CON4.5(CLK) R30.2

Not connected (* = marked no-connect by the designer): CON1 B(7) E(6) F(5) G; CON2 B(7) E(6) F(5) G; CON3 4(ID)*; CON4 11(GND)* 12(GND)*; CON5 1 3 5; ICON1 2* 4* 6*; ICON2 4(ID)*; IU1 1(INT0/PB14) 2(CPO1/PB13) 3(CPO0/PB12) 4(X32I) 5(X32O) 6(I2C1SCL/PA11) 7(I2C1SDA/PA10) 8(I2C0SCL/PA9) 9(I2C0SDA/PA8) 23(PB2/RTS0) 24(PB3/CTS0) 25(PC3/SDO00) 26(PC2/SDI00) 27(PC1/SPCLK0) 28(PC0/SS00) 30(PB11/TM3) 31(PB10/SS01/TM2) 32(PB9/SS11/TM1) 37(PA15/PWM3) 38(PA14/PWM2) 39(PA13/PWM1) 40(PA12/PWM0) 44(PA0/ADC0) 46(PA2/ADC2) 47(PA3/ADC3) 48(PA4/ADC4) 49(ADC/PA5) 50(ADC6/PA6) 51(ADC7/PA7) 53(CPN0/PC7) 54(CPP0/PC6) 55(CPN1/PC15) 56(CPP1/PC14) 57(INT1/PB15) 64(STADC/TM0/PB8); SW2 2* 3*; SW3 2* 3*

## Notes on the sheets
sheet 1
- nuvoTon
- NuTiny-EVB-NUC505_QFN88   V1.5
- NUC505YO13Y
- NuTiny-EVB-NUC505_QFN88
sheet 2
- +
- MIC
- 1
- -
- 1-2 Short
- C-E Right channel
- D-F Left channel
- B
- E
- D
- A
- G
- C
- F
- LINE IN
- HP OUT
- NuTiny-EVB-NUC505_QFN88
sheet 3
- ICE
- VCC
- ICE_Status
- VCOM switch
- DAT
- CLK
- RST
- nuvoTon
- Nu-Link-Me V2.0
- GND
- 12M Oscillators
- SWD connect
- power switch
- Nu-Link-Me V3.0
- NHS-NUC505-0-CY-3E01
sheet 4
- 1
- Power Setting
- S4
- S3
- S2
- S1
- PB4
- PB3
- PA10
- PA9
- 0
- 1
- 1
- 0
- ICE-Ext.-SPI
- 0
- 1
- 1
- 1
- ICE-SPI
- 1
- 0
- 1
- 1
- ICP
- 1
- 1
- 1
- 1
- 0
- 1
- 0
- 1
- Ext.-SPI
- USB
- 1
- 1
- 1
- 1
- SPI
- S
- S
- S
- S
- 4
- 3
- 2
- 1
- 1
- 0
- Reset
- NuTiny-EVB-NUC505_QFN88
- RTC Wake-up
sheet 5
- VCC5
- VCC33
- GND
- NuTiny-EVB-NUC505_QFN88
sheet 6
- VCC33
- ICE_DAT
- TXD
- ICE_CLK
- GND
- RESET
- RXD
- NuTiny-EVB-NUC505_QFN88
